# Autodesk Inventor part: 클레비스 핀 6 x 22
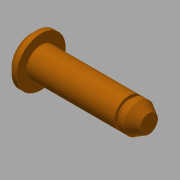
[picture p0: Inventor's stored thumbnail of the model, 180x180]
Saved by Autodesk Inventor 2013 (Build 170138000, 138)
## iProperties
IsCustomPart: 1
Created: 2017-08
Part Number: 클레비스 핀 6 x 22
Material: 강철
Description: 머리가 있는 클레비스 핀
Document SubType Name: Modeling
Standard: ISO 2341
Designer: mduedu
Standard Revision: Second edition 1986-11-01
Standards Organization: ISO
Language: ko-KR
Size Designation: B - 6 x 24
Categories: <MemberInstance><Categories><Category DisplayName="조임쇠" InternalName="e4da775c-781d-43d5-af7c-5136215cf5a6" Mnemonic="FSTN"><Category DisplayName="핀" InternalNa
Density: 7.85 g/cm^3
Mass: 5.79818 g
Surface Area: 6.11846 cm^2
Volume: 0.738621 cm^3
Author: mduedu
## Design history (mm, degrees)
sketch "스케치1"
  geometry: L1 (-2, 0)-(-2, 5); L2 (-2, 5)-(0, 5); L3 (0, 5)-(0, 3); L4 (0, 3)-(22, 3); L5 (22, 3)-(22, 0); L6 (-2, 0)-(22, 0); L7 (-7, 0)-(28, 0) reference; L8 (0, -1.96)-(0, 6.16) reference; C1 r 0.8 at (18.8, 0)
  constraints: 12 end point, 3 parallel, 2 collinear, 2 perpendicular, 1 centre point, 1 point on line, 1 vertical
  dimensions: "d0" = 6 diameter of L4 L6 (= NND); "d1" = 10 diameter of L2 L6 (= KOD); "d2" = 2 distance of L1.end L2.end (= KOH); "d3" = 22 distance of L3.end L4.end (= NLG); "d5" = 3.2 distance from line of L5 C1.centre (= DIST); "d6" = 1.6 diameter of C1 (= BOR)
revolve "본체" stored, may be unused: angle "d4" = 90 deg
workplane "Work Plane1"
node "작업 평면4"
sketch "스케치2"
  geometry: C1 r 3 at (0, 0) reference; C2 r 2.425 at (0, 0); 1 further point
  constraints: 1 centre point, 1 coincident
  dimensions: "d33" = 4.85 diameter of C2
extrude "돌출2" cut sketch "스케치2" distance "d34" = 0.7; taper "d35" = 0 deg
body "Solid1"
chamfer "모따기1" distance "d9" = 1 (= PHH2); stored, may be unused: angle "d10" = 45 deg (= FAWI2), second distance "d16" = 1 (= PHH2)
chamfer "모따기2" distance "d11" = 2 (= PHH1); stored, may be unused: angle "d12" = 30 deg (= FAWI1), second distance "d17" = 2 (= PHH1)
other parameters: "PHH1" = 2 [user parameter; used in 2 equation terms], "PHH2" = 1 [user parameter; used in 2 equation terms], "KOD" = 10 [user parameter; used in 1 equation term], "KOH" = 2 [user parameter; used in 1 equation term], "NND" = 6 [user parameter; used in 1 equation term], "FAWI1" = 30 deg [user parameter; used in 1 equation term], "FAWI2" = 45 deg [user parameter; used in 1 equation term], "DIST" = 3.2 [user parameter; used in 1 equation term], "BOR" = 1.6 [user parameter; used in 1 equation term], "NLG" = 22 [user parameter; used in 1 equation term], "d13" = 0, "d14" = 0, "d30" = 0, "d32" = 18
